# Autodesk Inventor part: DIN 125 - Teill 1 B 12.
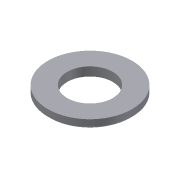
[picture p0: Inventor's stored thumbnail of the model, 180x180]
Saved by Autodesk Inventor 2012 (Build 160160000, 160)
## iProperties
Created: 2001-01
Part Number: DIN 125 - Teill 1 B 12.
Material: Steel, Mild
Document SubType Name: Modeling
Description: Unterlegscheibe DIN 125-B 12.
Standard: DIN 125 - Teill 1
Density: 7.86 g/cm^3
Company: CAD-Verlag
+MSCProtocol1+ProtocolID: P00040924060837034
+MSCProtocol2+Protocol: P00040924060837034<@PID>[Version]<@EL>Version=2.2<@EL>[Data]<@EL>Form=B{nd<@EL>mass=0.00627{kg<@EL>h=2.5{mm<@EL>Dd=24{mm<@EL>d=13{mm<@EL>Ds=12{mm<@EL>[Files]<@E
Control State: 0
Master: False
Checked Out: False
Shininess: 20.0
Length Units: 11269
Angle Units: 11279
Time Units: 11290
Mass Units: 11283
Length Display Precision: 3
Angle Display Precision: 2
BOM1: Unterlegscheibe
BOM2: B 12
BOM3: DIN 125 - Teill 1
Density: 7.860000000000001
Volumn: 0.2817125037336222
Area: 4.105336124320381
PropertySet Name: Model Information
Author: Jürgen Kronas
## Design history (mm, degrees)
node "WorkPlane1"
node "WorkPlane3"
node "Sketch1"
node "WorkPoint2"
extrude "ExtrusionBlind1" new body distance "d3" = 2.5 (= prf_h); taper "d4" = 0 deg
  node "Sketch2" dims "d2" = 24 (= prf_dd)
node "Sketch3"
node "WorkPoint1"
sketch "Sketch4"
  geometry: C1 r 12 at (0, 0) reference
hole "Hole1" sketch "Sketch4" diameter "d6" = 13 (= prf_d); stored, may be unused: countersink angle "d10" = 60 deg, drill point angle "d12" = 118 deg; dims "d7" = 6, "d8" = 4, "d9" = 2, "d11" = 8
chamfer "Chamfer1" distance "d13" = 0.625 (= 0.25 x prf_h); stored, may be unused: angle "d14" = 45 deg, second distance "d20" = 0.625 (= 0.25 x prf_h)
node "WorkAxis1"
node "MSC_A1"
node "MSC_PT1"
node "MSC_PT2"
node "Volumenkörper1"
node "Volumenkörpern"
node "Oberflächenkörpern"
other parameters: "prf_d" = 13 [user parameter; used in 1 equation term], "prf_dd" = 24 [user parameter; used in 1 equation term], "prf_h" = 2.5 [user parameter; used in 4 equation terms], "d0" = -2.5 (computed from prf_h), "d1" = 15 (derived), "d5" = 0, "d16" = 0, "d18" = 0, "d19" = 0
